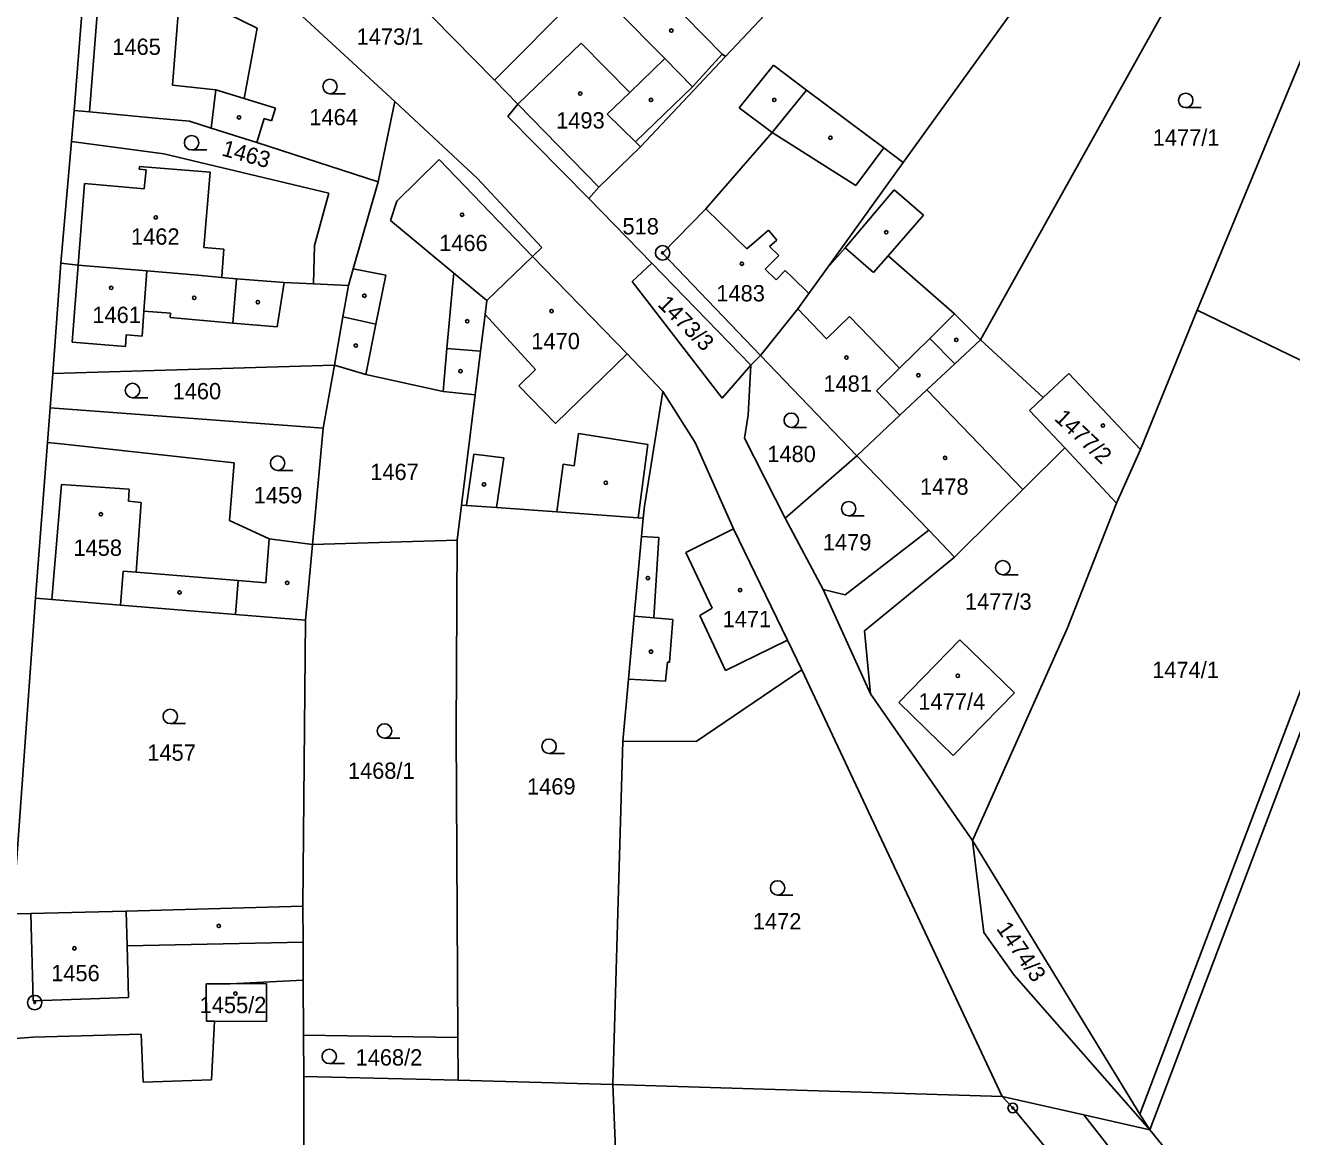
# Model space of a CAD drawing. Extents: x -763296 to -761805, y -1153670 to -1152034.
# Drawn here: x -762755.5 to -762623.5, y -1152400.8 to -1152285 of the extents above; entities that cross this region are included whole.
import ezdxf

# ---------------------------------------------------------------- set-up
doc = ezdxf.new("R2010")
doc.units = 0
for name, color, linetype in [('Vrstva 1', 7, 'Continuous'), ('Vrstva 17', 7, 'Continuous'), ('Vrstva 18', 7, 'Continuous'), ('Vrstva 19', 7, 'Continuous'), ('Vrstva 24', 7, 'Continuous'), ('Vrstva 25', 7, 'Continuous'), ('Vrstva 4', 7, 'Continuous'), ('Vrstva 6', 7, 'Continuous')]:
    doc.layers.add(name, color=color, linetype=linetype)

msp = doc.modelspace()

# ---------------------------------------------------------------- linework, layer by layer
at = {"layer": 'Vrstva 1'}
for p, q in [((-762655.97, -1152317.77), (-762623.06, -1152258.78)), ((-762612.3, -1152263.79), (-762633.4, -1152314.71)), ((-762644.04, -1152271.62), (-762664.02, -1152299.3)), ((-762748.9, -1152274.7), (-762750.41, -1152293.9)), ((-762734.79, -1152276.55), (-762716.98, -1152292.95)), ((-762706.61, -1152290.74), (-762693.36, -1152277.38)), ((-762682.55, -1152288.27), (-762672.94, -1152278.08)), ((-762690.66, -1152280.1), (-762682.89, -1152288.01)), ((-762706.61, -1152290.74), (-762716.31, -1152280.86)), ((-762731.33, -1152285.31), (-762734.39, -1152283.83)), ((-762731.33, -1152285.31), (-762732.7, -1152292.64)), ((-762682.89, -1152288.01), (-762682.55, -1152288.27)), ((-762691.41, -1152297.66), (-762682.55, -1152288.27)), ((-762681.1, -1152293.63), (-762677.55, -1152289.18)), ((-762677.55, -1152289.18), (-762674.11, -1152291.76)), ((-762704.17, -1152293.23), (-762706.61, -1152290.74)), ((-762674.11, -1152291.76), (-762666.03, -1152297.79)), ((-762729.44, -1152293.64), (-762732.7, -1152292.64)), ((-762718.74, -1152301.34), (-762716.98, -1152292.95)), ((-762716.98, -1152292.95), (-762708.41, -1152300.94)), ((-762705.22, -1152294.52), (-762704.17, -1152293.23)), ((-762750.41, -1152293.9), (-762750.69, -1152297.11)), ((-762750.41, -1152293.9), (-762748.81, -1152294.04)), ((-762748.81, -1152294.04), (-762741.92, -1152294.7)), ((-762741.92, -1152294.7), (-762738.4, -1152295.01)), ((-762731.38, -1152297.24), (-762730.6, -1152294.72)), ((-762730.6, -1152294.72), (-762729.85, -1152294.98)), ((-762729.85, -1152294.98), (-762729.44, -1152293.64)), ((-762696.77, -1152303.05), (-762705.22, -1152294.52)), ((-762677.68, -1152296.18), (-762681.1, -1152293.63)), ((-762738.4, -1152295.01), (-762736.14, -1152295.74)), ((-762736.14, -1152295.74), (-762731.38, -1152297.24)), ((-762750.69, -1152297.11), (-762751.78, -1152309.81)), ((-762741.06, -1152298.39), (-762750.69, -1152297.11)), ((-762731.38, -1152297.24), (-762718.74, -1152301.34)), ((-762684.57, -1152304.12), (-762677.68, -1152296.18)), ((-762741.06, -1152298.39), (-762723.87, -1152302.52)), ((-762695.75, -1152301.89), (-762691.41, -1152297.66)), ((-762666.03, -1152297.79), (-762664.02, -1152299.3)), ((-762664.02, -1152299.3), (-762671.95, -1152310.3)), ((-762721.33, -1152310.38), (-762718.74, -1152301.34)), ((-762708.41, -1152300.94), (-762701.67, -1152308.15)), ((-762723.87, -1152302.52), (-762725.35, -1152307.95)), ((-762696.77, -1152303.05), (-762695.75, -1152301.89)), ((-762670.08, -1152308.2), (-762664.97, -1152302.14)), ((-762664.97, -1152302.14), (-762661.9, -1152304.8)), ((-762690.22, -1152309.79), (-762696.77, -1152303.05)), ((-762689.11, -1152308.75), (-762684.57, -1152304.12)), ((-762661.9, -1152304.8), (-762665.59, -1152309.02)), ((-762725.35, -1152307.95), (-762725.48, -1152311.95)), ((-762702.65, -1152309.09), (-762707.39, -1152313.7)), ((-762701.67, -1152308.15), (-762702.65, -1152309.09)), ((-762702.65, -1152309.09), (-762692.77, -1152319.23)), ((-762678.9, -1152319.4), (-762689.11, -1152308.75)), ((-762671.95, -1152310.3), (-762670.08, -1152308.2)), ((-762658.66, -1152315.09), (-762665.59, -1152309.02)), ((-762751.78, -1152309.81), (-762752.63, -1152321.29)), ((-762749.98, -1152310.02), (-762751.78, -1152309.81)), ((-762742.85, -1152310.61), (-762749.98, -1152310.02)), ((-762737.52, -1152311.05), (-762742.85, -1152310.61)), ((-762721.83, -1152312.12), (-762721.33, -1152310.38)), ((-762692.26, -1152311.7), (-762690.22, -1152309.79)), ((-762679.91, -1152320.41), (-762690.22, -1152309.79)), ((-762671.95, -1152310.3), (-762673.87, -1152312.97)), ((-762735.04, -1152311.28), (-762737.52, -1152311.05)), ((-762733.48, -1152311.43), (-762735.04, -1152311.28)), ((-762728.52, -1152311.81), (-762733.48, -1152311.43)), ((-762725.48, -1152311.95), (-762728.52, -1152311.81)), ((-762721.83, -1152312.12), (-762725.48, -1152311.95)), ((-762682.9, -1152323.86), (-762692.26, -1152311.7)), ((-762722.4, -1152315.38), (-762721.83, -1152312.12)), ((-762675.01, -1152314.54), (-762673.87, -1152312.97)), ((-762707.39, -1152313.7), (-762707.57, -1152315.15)), ((-762675.01, -1152314.54), (-762678.9, -1152319.4)), ((-762723.29, -1152320.41), (-762722.4, -1152315.38)), ((-762708.05, -1152318.97), (-762707.57, -1152315.15)), ((-762655.97, -1152317.77), (-762658.66, -1152315.09)), ((-762633.4, -1152314.71), (-762639.29, -1152329.22)), ((-762611.61, -1152325.23), (-762633.4, -1152314.71)), ((-762655.97, -1152317.77), (-762658.65, -1152320.29)), ((-762655.97, -1152317.77), (-762649.44, -1152323.78)), ((-762708.61, -1152323.52), (-762708.05, -1152318.97)), ((-762692.77, -1152319.23), (-762689.06, -1152323.18)), ((-762678.9, -1152319.4), (-762679.91, -1152320.41)), ((-762678.9, -1152319.4), (-762668.84, -1152329.86)), ((-762752.63, -1152321.29), (-762723.29, -1152320.41)), ((-762724.45, -1152326.98), (-762723.29, -1152320.41)), ((-762723.29, -1152320.41), (-762720.01, -1152321.4)), ((-762679.91, -1152320.41), (-762682.9, -1152323.86)), ((-762680.18, -1152325.62), (-762679.91, -1152320.41)), ((-762658.65, -1152320.29), (-762661.57, -1152323.01)), ((-762752.63, -1152321.29), (-762752.9, -1152324.88)), ((-762720.01, -1152321.4), (-762711.96, -1152323.17)), ((-762646.77, -1152321.28), (-762649.44, -1152323.78)), ((-762639.29, -1152329.22), (-762646.77, -1152321.28)), ((-762711.96, -1152323.17), (-762708.61, -1152323.52)), ((-762710.04, -1152335), (-762708.61, -1152323.52)), ((-762689.06, -1152323.18), (-762690.99, -1152335.13)), ((-762689.06, -1152323.18), (-762685.69, -1152328.47)), ((-762661.57, -1152323.01), (-762664.37, -1152325.64)), ((-762649.44, -1152323.78), (-762650.87, -1152325.13)), ((-762752.9, -1152324.88), (-762753.18, -1152328.47)), ((-762724.45, -1152326.98), (-762752.9, -1152324.88)), ((-762650.87, -1152325.13), (-762647.18, -1152329.05)), ((-762680.56, -1152328.03), (-762680.18, -1152325.62)), ((-762664.37, -1152325.64), (-762668.84, -1152329.86)), ((-762638.33, -1152400.1), (-762610.25, -1152325.9)), ((-762725.57, -1152339.09), (-762724.45, -1152326.98)), ((-762753.18, -1152328.47), (-762754.43, -1152344.69)), ((-762751.46, -1152328.65), (-762753.18, -1152328.47)), ((-762751.46, -1152328.65), (-762733.74, -1152330.6)), ((-762685.69, -1152328.47), (-762681.7, -1152337.48)), ((-762676.31, -1152336.37), (-762680.56, -1152328.03)), ((-762651.57, -1152333.39), (-762647.18, -1152329.05)), ((-762647.18, -1152329.05), (-762641.78, -1152334.79)), ((-762668.84, -1152329.86), (-762676.31, -1152336.37)), ((-762661.36, -1152337.62), (-762668.84, -1152329.86)), ((-762641.78, -1152334.79), (-762639.29, -1152329.22)), ((-762733.74, -1152330.6), (-762734.22, -1152336.6)), ((-762654.31, -1152336.1), (-762651.57, -1152333.39)), ((-762710.5, -1152338.66), (-762710.04, -1152335)), ((-762709.54, -1152335.04), (-762710.04, -1152335)), ((-762706.4, -1152335.26), (-762709.54, -1152335.04)), ((-762700.12, -1152335.72), (-762706.4, -1152335.26)), ((-762691.65, -1152336.33), (-762700.12, -1152335.72)), ((-762690.99, -1152335.13), (-762691.1, -1152336.37)), ((-762646.91, -1152347.78), (-762641.78, -1152334.79)), ((-762730.07, -1152338.53), (-762734.22, -1152336.6)), ((-762691.1, -1152336.37), (-762691.65, -1152336.33)), ((-762691.28, -1152338.29), (-762691.1, -1152336.37)), ((-762676.31, -1152336.37), (-762672.36, -1152343.8)), ((-762658.67, -1152340.41), (-762654.31, -1152336.1)), ((-762692.04, -1152346.56), (-762691.28, -1152338.29)), ((-762676.06, -1152349.06), (-762681.7, -1152337.48)), ((-762670.06, -1152344.34), (-762661.36, -1152337.62)), ((-762730.07, -1152338.53), (-762725.57, -1152339.09)), ((-762726.3, -1152346.99), (-762725.57, -1152339.09)), ((-762725.57, -1152339.09), (-762710.5, -1152338.66)), ((-762710.5, -1152338.66), (-762710.59, -1152358.63)), ((-762668.04, -1152348.09), (-762658.67, -1152340.41)), ((-762754.43, -1152344.69), (-762756.81, -1152377.58)), ((-762754.43, -1152344.69), (-762752.74, -1152344.84)), ((-762752.74, -1152344.84), (-762745.59, -1152345.41)), ((-762672.36, -1152343.8), (-762670.06, -1152344.34)), ((-762672.36, -1152343.8), (-762667.44, -1152354.65)), ((-762745.59, -1152345.41), (-762733.61, -1152346.39)), ((-762733.61, -1152346.39), (-762726.3, -1152346.99)), ((-762726.3, -1152346.99), (-762726.57, -1152376.8)), ((-762692.47, -1152351.19), (-762692.04, -1152346.56)), ((-762667.44, -1152354.65), (-762668.04, -1152348.09)), ((-762656.79, -1152369.93), (-762646.91, -1152347.78)), ((-762676.06, -1152349.06), (-762674.59, -1152352.18)), ((-762658.12, -1152349.03), (-762664.47, -1152355.57)), ((-762652.43, -1152354.56), (-762658.12, -1152349.03)), ((-762692.65, -1152353.15), (-762692.47, -1152351.19)), ((-762685.59, -1152359.64), (-762674.59, -1152352.18)), ((-762653.69, -1152396.61), (-762674.59, -1152352.18)), ((-762693.24, -1152359.59), (-762692.65, -1152353.15)), ((-762656.79, -1152369.93), (-762667.44, -1152354.65)), ((-762658.82, -1152361.1), (-762652.43, -1152354.56)), ((-762664.47, -1152355.57), (-762658.82, -1152361.1)), ((-762710.59, -1152358.63), (-762710.42, -1152390.48)), ((-762694.27, -1152395.38), (-762693.24, -1152359.59)), ((-762693.24, -1152359.59), (-762685.59, -1152359.64)), ((-762655.61, -1152379.53), (-762656.79, -1152369.93)), ((-762754.92, -1152377.55), (-762756.81, -1152377.58)), ((-762744.99, -1152377.29), (-762754.92, -1152377.55)), ((-762744.99, -1152377.29), (-762726.57, -1152376.8)), ((-762726.57, -1152376.8), (-762726.55, -1152380.53)), ((-762726.55, -1152380.53), (-762726.54, -1152384.48)), ((-762652.45, -1152383.97), (-762655.61, -1152379.53)), ((-762726.54, -1152384.48), (-762734.15, -1152384.86)), ((-762726.54, -1152384.48), (-762726.51, -1152390.23)), ((-762638.33, -1152400.1), (-762652.45, -1152383.97)), ((-762736.6, -1152388.76), (-762736.64, -1152384.86)), ((-762736.64, -1152384.86), (-762734.15, -1152384.86)), ((-762734.15, -1152384.86), (-762730.38, -1152384.85)), ((-762730.38, -1152384.85), (-762730.37, -1152388.79)), ((-762735.8, -1152388.76), (-762736.6, -1152388.76)), ((-762736.11, -1152394.88), (-762735.8, -1152388.76)), ((-762730.37, -1152388.79), (-762735.8, -1152388.76)), ((-762757, -1152390.62), (-762754.69, -1152390.45)), ((-762754.69, -1152390.45), (-762743.41, -1152390.13)), ((-762743.41, -1152390.13), (-762743.23, -1152395.13)), ((-762726.51, -1152390.23), (-762710.42, -1152390.48)), ((-762726.51, -1152390.23), (-762726.49, -1152394.53)), ((-762710.42, -1152390.48), (-762710.4, -1152394.92)), ((-762743.23, -1152395.13), (-762736.11, -1152394.88)), ((-762726.49, -1152394.53), (-762710.4, -1152394.92)), ((-762726.42, -1152417.35), (-762726.49, -1152394.53)), ((-762710.4, -1152394.92), (-762694.27, -1152395.38)), ((-762693.4, -1152416.82), (-762694.27, -1152395.38)), ((-762694.27, -1152395.38), (-762653.69, -1152396.61)), ((-762652.6, -1152397.81), (-762653.69, -1152396.61)), ((-762653.69, -1152396.61), (-762645.21, -1152398.54)), ((-762640.33, -1152412.61), (-762652.6, -1152397.81)), ((-762645.21, -1152398.54), (-762638.33, -1152400.1))]:
    msp.add_line(p, q, dxfattribs=at)
at = {"layer": 'Vrstva 24'}
for centre, radius in [((-762689.09, -1152308.72), 0.75), ((-762689.09, -1152308.72), 0.1), ((-762754.52, -1152386.83), 0.75), ((-762754.52, -1152386.83), 0.1), ((-762652.6, -1152397.81), 0.5), ((-762652.6, -1152397.81), 0.1)]:
    msp.add_circle(centre, radius, dxfattribs=at)
at = {"layer": 'Vrstva 25'}
for p, q in [((-762723.75, -1152292.14), (-762722.15, -1152292.14)), ((-762634.58, -1152293.59), (-762632.98, -1152293.59)), ((-762738.17, -1152298), (-762736.57, -1152298)), ((-762744.33, -1152323.81), (-762742.73, -1152323.81)), ((-762675.69, -1152326.91), (-762674.09, -1152326.91)), ((-762729.21, -1152331.38), (-762727.61, -1152331.38)), ((-762669.7, -1152336.12), (-762668.1, -1152336.12)), ((-762653.64, -1152342.27), (-762652.04, -1152342.27)), ((-762740.39, -1152357.77), (-762738.79, -1152357.77)), ((-762718.07, -1152359.28), (-762716.47, -1152359.28)), ((-762700.92, -1152360.88), (-762699.32, -1152360.88)), ((-762677.11, -1152375.63), (-762675.51, -1152375.63)), ((-762723.83, -1152393.19), (-762722.23, -1152393.19))]:
    msp.add_line(p, q, dxfattribs=at)
for centre, radius in [((-762688.18, -1152285.56), 0.175), ((-762723.75, -1152291.39), 0.75), ((-762697.67, -1152292.13), 0.175), ((-762634.58, -1152292.84), 0.75), ((-762690.3, -1152292.79), 0.175), ((-762677.45, -1152292.79), 0.175), ((-762733.23, -1152294.61), 0.175), ((-762738.17, -1152297.25), 0.75), ((-762671.61, -1152296.73), 0.175), ((-762741.91, -1152305.03), 0.175), ((-762709.99, -1152304.75), 0.175), ((-762665.78, -1152306.57), 0.175), ((-762680.82, -1152309.86), 0.175), ((-762746.55, -1152312.38), 0.175), ((-762737.89, -1152313.41), 0.175), ((-762720.17, -1152313.19), 0.175), ((-762731.26, -1152313.86), 0.175), ((-762700.66, -1152314.79), 0.175), ((-762709.44, -1152315.85), 0.175), ((-762721.06, -1152318.38), 0.175), ((-762658.49, -1152317.79), 0.175), ((-762669.94, -1152319.63), 0.175), ((-762710.15, -1152321.04), 0.175), ((-762744.33, -1152323.06), 0.75), ((-762662.43, -1152321.48), 0.175), ((-762675.69, -1152326.16), 0.75), ((-762643.21, -1152326.72), 0.175), ((-762729.21, -1152330.63), 0.75), ((-762659.65, -1152330.08), 0.175), ((-762707.7, -1152332.85), 0.175), ((-762695.02, -1152332.68), 0.175), ((-762669.7, -1152335.37), 0.75), ((-762747.62, -1152335.95), 0.175), ((-762653.64, -1152341.52), 0.75), ((-762728.21, -1152343.11), 0.175), ((-762690.62, -1152342.61), 0.175), ((-762739.42, -1152344.1), 0.175), ((-762681.02, -1152343.85), 0.175), ((-762690.3, -1152350.27), 0.175), ((-762658.33, -1152352.79), 0.175), ((-762740.39, -1152357.02), 0.75), ((-762718.07, -1152358.53), 0.75), ((-762700.92, -1152360.13), 0.75), ((-762677.11, -1152374.88), 0.75), ((-762735.34, -1152378.84), 0.175), ((-762750.38, -1152381.18), 0.175), ((-762733.61, -1152385.89), 0.175), ((-762723.83, -1152392.44), 0.75)]:
    msp.add_circle(centre, radius, dxfattribs=at)
at = {"layer": 'Vrstva 4'}
for p, q in [((-762747.57, -1152277.99), (-762748.81, -1152294.04)), ((-762739.17, -1152278.76), (-762740.15, -1152291.24)), ((-762688.86, -1152288.47), (-762693.96, -1152283.32)), ((-762697.58, -1152286.87), (-762704.17, -1152293.23)), ((-762697.58, -1152286.87), (-762692.52, -1152292.03)), ((-762682.89, -1152288.01), (-762685.97, -1152291.41)), ((-762692.52, -1152292.03), (-762688.86, -1152288.47)), ((-762688.86, -1152288.47), (-762685.97, -1152291.41)), ((-762740.15, -1152291.24), (-762735.65, -1152291.73)), ((-762735.65, -1152291.73), (-762736.14, -1152295.74)), ((-762735.65, -1152291.73), (-762732.7, -1152292.64)), ((-762694.85, -1152294.29), (-762692.52, -1152292.03)), ((-762685.97, -1152291.41), (-762691.91, -1152297.17)), ((-762677.68, -1152296.18), (-762674.11, -1152291.76)), ((-762704.17, -1152293.23), (-762695.75, -1152301.89)), ((-762691.91, -1152297.17), (-762694.85, -1152294.29)), ((-762691.91, -1152297.17), (-762691.41, -1152297.66)), ((-762677.68, -1152296.18), (-762668.96, -1152301.71)), ((-762668.96, -1152301.71), (-762666.03, -1152297.79)), ((-762743.63, -1152300.01), (-762743.6, -1152299.72)), ((-762742.92, -1152300.08), (-762743.63, -1152300.01)), ((-762743.6, -1152299.72), (-762736.24, -1152300.33)), ((-762743.1, -1152302.05), (-762742.92, -1152300.08)), ((-762716.78, -1152303.32), (-762712.39, -1152299.01)), ((-762712.39, -1152299.01), (-762702.65, -1152309.09)), ((-762736.24, -1152300.33), (-762736.89, -1152308.18)), ((-762749.32, -1152301.5), (-762749.98, -1152310.02)), ((-762749.32, -1152301.5), (-762743.1, -1152302.05)), ((-762717.46, -1152305.36), (-762716.78, -1152303.32)), ((-762710.86, -1152310.83), (-762717.46, -1152305.36)), ((-762684.57, -1152304.12), (-762680.32, -1152308.29)), ((-762678.82, -1152307.02), (-762678.05, -1152306.37)), ((-762678.05, -1152306.37), (-762677.18, -1152307.4)), ((-762680.32, -1152308.29), (-762678.82, -1152307.02)), ((-762677.18, -1152307.4), (-762677.94, -1152308.05)), ((-762736.89, -1152308.18), (-762734.8, -1152308.35)), ((-762734.8, -1152308.35), (-762735.03, -1152311.14)), ((-762676.98, -1152309), (-762678.39, -1152310.42)), ((-762677.94, -1152308.05), (-762676.98, -1152309)), ((-762667.11, -1152310.76), (-762670.08, -1152308.2)), ((-762667.11, -1152310.76), (-762665.59, -1152309.02)), ((-762750.62, -1152318.04), (-762749.98, -1152310.02)), ((-762742.85, -1152310.61), (-762743.14, -1152314.78)), ((-762717.94, -1152311.06), (-762721.33, -1152310.38)), ((-762678.39, -1152310.42), (-762677.27, -1152311.53)), ((-762677.27, -1152311.53), (-762676.31, -1152310.56)), ((-762676.31, -1152310.56), (-762675.6, -1152311.25)), ((-762735.03, -1152311.14), (-762735.04, -1152311.28)), ((-762733.48, -1152311.43), (-762733.88, -1152316.04)), ((-762729.24, -1152316.44), (-762728.52, -1152311.81)), ((-762717.94, -1152311.06), (-762718.96, -1152316.15)), ((-762711.56, -1152318.68), (-762710.95, -1152311.87)), ((-762710.95, -1152311.87), (-762710.86, -1152310.83)), ((-762707.39, -1152313.7), (-762710.86, -1152310.83)), ((-762675.6, -1152311.25), (-762673.87, -1152312.97)), ((-762675.01, -1152314.54), (-762672, -1152317.68)), ((-762743.14, -1152314.78), (-762743.32, -1152317.41)), ((-762743.14, -1152314.78), (-762740.36, -1152315)), ((-762740.36, -1152315), (-762740.4, -1152315.47)), ((-762740.4, -1152315.47), (-762733.88, -1152316.04)), ((-762718.96, -1152316.15), (-762722.4, -1152315.38)), ((-762702.34, -1152320.88), (-762707.57, -1152315.15)), ((-762672, -1152317.68), (-762669.62, -1152315.36)), ((-762669.62, -1152315.36), (-762664.41, -1152320.74)), ((-762658.66, -1152315.09), (-762661.26, -1152317.65)), ((-762744.98, -1152317.25), (-762745.07, -1152318.47)), ((-762743.32, -1152317.41), (-762744.98, -1152317.25)), ((-762733.88, -1152316.04), (-762729.24, -1152316.44)), ((-762718.96, -1152316.15), (-762720.01, -1152321.4)), ((-762745.07, -1152318.47), (-762750.62, -1152318.04)), ((-762661.26, -1152317.65), (-762664.41, -1152320.74)), ((-762661.26, -1152317.65), (-762658.65, -1152320.29)), ((-762711.96, -1152323.17), (-762711.56, -1152318.68)), ((-762711.56, -1152318.68), (-762708.05, -1152318.97)), ((-762692.77, -1152319.23), (-762700.26, -1152326.5)), ((-762704.08, -1152322.58), (-762702.34, -1152320.88)), ((-762664.41, -1152320.74), (-762666.81, -1152323.09)), ((-762700.26, -1152326.5), (-762704.08, -1152322.58)), ((-762666.81, -1152323.09), (-762664.37, -1152325.64)), ((-762651.57, -1152333.39), (-762661.57, -1152323.01)), ((-762698.32, -1152330.91), (-762697.85, -1152327.54)), ((-762697.85, -1152327.54), (-762690.64, -1152328.68)), ((-762690.64, -1152328.68), (-762691.65, -1152336.33)), ((-762708.77, -1152329.69), (-762709.54, -1152335.04)), ((-762705.63, -1152330.07), (-762708.77, -1152329.69)), ((-762706.4, -1152335.26), (-762705.63, -1152330.07)), ((-762700.12, -1152335.72), (-762699.44, -1152330.75)), ((-762699.44, -1152330.75), (-762698.32, -1152330.91)), ((-762752.74, -1152344.84), (-762751.74, -1152332.86)), ((-762751.74, -1152332.86), (-762744.66, -1152333.34)), ((-762744.66, -1152333.34), (-762744.76, -1152334.6)), ((-762744.76, -1152334.6), (-762743.41, -1152334.72)), ((-762743.41, -1152334.72), (-762743.93, -1152341.99)), ((-762691.28, -1152338.29), (-762689.5, -1152338.39)), ((-762681.7, -1152337.48), (-762686.67, -1152339.94)), ((-762661.36, -1152337.62), (-762658.67, -1152340.41)), ((-762730.45, -1152343.11), (-762730.07, -1152338.53)), ((-762689.5, -1152338.39), (-762689.99, -1152346.74)), ((-762686.67, -1152339.94), (-762683.92, -1152345.75)), ((-762745.3, -1152341.87), (-762745.59, -1152345.41)), ((-762743.93, -1152341.99), (-762745.3, -1152341.87)), ((-762743.93, -1152341.99), (-762733.32, -1152342.85)), ((-762733.32, -1152342.85), (-762733.61, -1152346.39)), ((-762733.32, -1152342.85), (-762730.45, -1152343.11)), ((-762683.92, -1152345.75), (-762685.2, -1152346.5)), ((-762689.99, -1152346.74), (-762692.04, -1152346.56)), ((-762689.99, -1152346.74), (-762688.04, -1152346.91)), ((-762688.04, -1152346.91), (-762688.36, -1152351.37)), ((-762685.2, -1152346.5), (-762682.52, -1152352.24)), ((-762682.52, -1152352.24), (-762676.06, -1152349.06)), ((-762688.58, -1152351.36), (-762688.78, -1152353.34)), ((-762688.36, -1152351.37), (-762688.58, -1152351.36)), ((-762688.78, -1152353.34), (-762692.65, -1152353.15)), ((-762754.92, -1152377.55), (-762754.69, -1152386.64)), ((-762744.89, -1152380.93), (-762744.99, -1152377.29)), ((-762726.55, -1152380.53), (-762744.89, -1152380.93)), ((-762744.75, -1152386.31), (-762744.89, -1152380.93)), ((-762754.69, -1152386.64), (-762744.75, -1152386.31))]:
    msp.add_line(p, q, dxfattribs=at)
at = {"layer": 'Vrstva 6'}
for p, q in [((-762611.61, -1152325.23), (-762639.37, -1152398.45)), ((-762639.37, -1152398.45), (-762656.79, -1152369.93)), ((-762645.21, -1152398.54), (-762630.65, -1152416.99)), ((-762638.33, -1152400.1), (-762639.37, -1152398.45)), ((-762638.33, -1152400.1), (-762626.43, -1152414.62))]:
    msp.add_line(p, q, dxfattribs=at)

# ---------------------------------------------------------------- texts
at = {"layer": 'Vrstva 17'}
msp.add_text('518', height=1.7, dxfattribs=at).set_placement((-762693.27, -1152306.8))
at = {"layer": 'Vrstva 18'}
for s, p in [('1473/1', (-762720.973, -1152287.04)), ('1464', (-762725.895, -1152295.43)), ('1477/1', (-762638.016, -1152297.55)), ('1460', (-762740.152, -1152323.98)), ('1480', (-762678.179, -1152330.52)), ('1467', (-762719.555, -1152332.39)), ('1459', (-762731.692, -1152334.82)), ('1479', (-762672.395, -1152339.72)), ('1477/3', (-762657.591, -1152345.9)), ('1474/1', (-762638.076, -1152353.02)), ('1457', (-762742.782, -1152361.64)), ('1468/1', (-762721.883, -1152363.52)), ('1469', (-762703.215, -1152365.16)), ('1472', (-762679.689, -1152379.21)), ('1468/2', (-762721.085, -1152393.39))]:
    msp.add_text(s, height=1.7, dxfattribs=at).set_placement(p)
for s, rotation, p in [('1463', 344.51952, (-762735.126, -1152298.564)), ('1473/3', 315.06949, (-762689.697, -1152314.18)), ('1474/3', 304.46977, (-762654.373, -1152379.12))]:
    msp.add_text(s, height=1.7, rotation=rotation, dxfattribs=at).set_placement(p)
at = {"layer": 'Vrstva 19'}
for s, p in [('1465', (-762746.432, -1152288.1)), ('1493', (-762700.182, -1152295.77)), ('1462', (-762744.479, -1152307.87)), ('1466', (-762712.375, -1152308.54)), ('1483', (-762683.489, -1152313.78)), ('1461', (-762748.507, -1152316.03)), ('1470', (-762702.762, -1152318.76)), ('1481', (-762672.334, -1152323.19)), ('1478', (-762662.265, -1152333.92)), ('1458', (-762750.482, -1152340.29)), ('1471', (-762682.837, -1152347.72)), ('1477/4', (-762662.434, -1152356.31)), ('1456', (-762752.802, -1152384.61)), ('1455/2', (-762737.332, -1152387.93))]:
    msp.add_text(s, height=1.7, dxfattribs=at).set_placement(p)
msp.add_text('1477/2', height=1.7, rotation=316.78836, dxfattribs=at).set_placement((-762648.356, -1152326.08))

doc.saveas('drawing.dxf')
